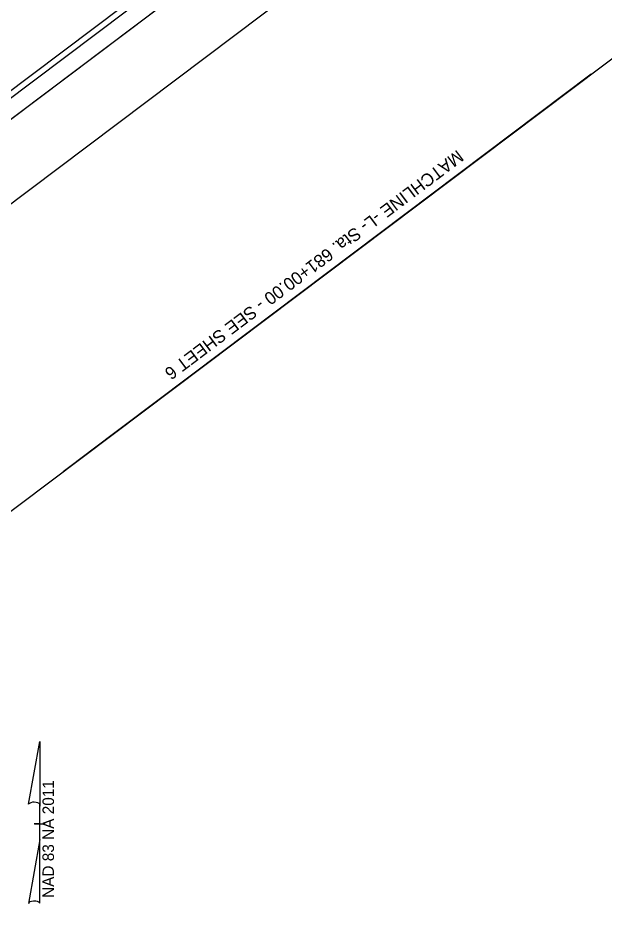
# Model space of a CAD drawing. Extents: x 1262337 to 1264328, y 775525 to 777528.
# Drawn here: x 1262790 to 1263223, y 776506 to 777181 of the extents above; entities that cross this region are included whole.
import ezdxf

# ---------------------------------------------------------------- set-up
doc = ezdxf.new("R2010")
doc.units = 0
for name, color, linetype in [('Matchline', 7, 'Continuous'), ('Old_Level_1', 7, 'Continuous'), ('Sheet Clip Boundary CELL', 7, 'Continuous'), ('Sheet Layout Plan Border', 7, 'Continuous'), ('Sheet Plan CELL', 7, 'Continuous'), ('Sheet Plan Layout CELL', 7, 'Continuous'), ('Sheet Plot Border Inside CELL', 7, 'Continuous'), ('Sheet Plot Border Outside CELL', 7, 'Continuous')]:
    doc.layers.add(name, color=color, linetype=linetype)

msp = doc.modelspace()

# ---------------------------------------------------------------- linework, layer by layer
at = {"layer": 'Matchline'}
for p, q in [((1263213.26, 777139.78), (1262822.87, 776845.73)), ((1263163.68, 777102.44), (1262841.99, 776860.14))]:
    msp.add_line(p, q, dxfattribs=at)
at = {"layer": 'Old_Level_1'}
for p, q in [((1262797.22, 776599.69), (1262805.44, 776646.04)), ((1262805.49, 776646.04), (1262805.44, 776646.04)), ((1262805.49, 776646.04), (1262805.44, 776646.04)), ((1262805.49, 776646.04), (1262805.47, 776598.24)), ((1262805.46, 776573.44), (1262805.47, 776599.64)), ((1262805.47, 776598.24), (1262805.47, 776599.59)), ((1262801.46, 776585.04), (1262801.41, 776585.04)), ((1262805.01, 776585.04), (1262801.46, 776585.04)), ((1262801.51, 776585.04), (1262809.51, 776585.04)), ((1262805.46, 776573.44), (1262797.09, 776526.19)), ((1262805.49, 776526.39), (1262805.46, 776573.44))]:
    msp.add_line(p, q, dxfattribs=at)
for centre, start_param, end_param in [((1262801.36, 776599.2), 0.216388, 2.908219), ((1262801.33, 776526.03), 0.201328, 3.141593)]:
    msp.add_ellipse(centre, major_axis=(4.23, -0.03), ratio=0.461098, start_param=start_param, end_param=end_param, dxfattribs=at)
at = {"layer": 'Sheet Clip Boundary CELL'}
msp.add_lwpolyline([(1263888.49, 776271.07), (1264108.83, 776437.03), (1263657.31, 777036.5), (1263449.04, 777317.16), (1262881.72, 776889.85), (1262608.34, 776683.94), (1263270.12, 775805.31)], close=True, dxfattribs=at)
at = {"layer": 'Sheet Layout Plan Border'}
msp.add_lwpolyline([(1264180.22, 776342.84), (1263337.92, 777461.13), (1262668.14, 776956.65), (1262782.01, 776805.47), (1262613.08, 776678.23), (1263341.52, 775711.12)], close=True, dxfattribs=at)
at = {"layer": 'Sheet Plan CELL'}
msp.add_lwpolyline([(1262469.12, 776869.36), (1263371.6, 775671.18), (1264210.31, 776302.91), (1263307.84, 777501.07)], close=True, dxfattribs=at)
at = {"layer": 'Sheet Plan Layout CELL'}
msp.add_lwpolyline([(1263371.64, 775671.18), (1264210.31, 776302.91), (1263307.85, 777501.06), (1262638.07, 776996.57), (1262782.01, 776805.47), (1262613.08, 776678.23)], close=True, dxfattribs=at)
at = {"layer": 'Sheet Plot Border Inside CELL'}
msp.add_lwpolyline([(1264304.66, 776181.82), (1263302.32, 777512.55), (1262459.63, 776877.83), (1263461.96, 775547.09)], close=True, dxfattribs=at)
at = {"layer": 'Sheet Plot Border Outside CELL'}
msp.add_lwpolyline([(1264328.45, 776183.46), (1263315.59, 777528.19), (1262440.94, 776869.39), (1263453.8, 775524.67)], close=True, dxfattribs=at)

# ---------------------------------------------------------------- texts
at = {"layer": 'Matchline'}
msp.add_text('MATCHLINE -L- Sta. 681+00.00 - SEE SHEET 6', height=9.375, rotation=216.98742, dxfattribs=at).set_placement((1263114.32, 777084.31))
at = {"layer": 'Old_Level_1'}
msp.add_text('NAD 83 NA 2011', height=8.5, rotation=89.97606, dxfattribs=at).set_placement((1262815.96, 776530.29))

doc.saveas('drawing.dxf')
